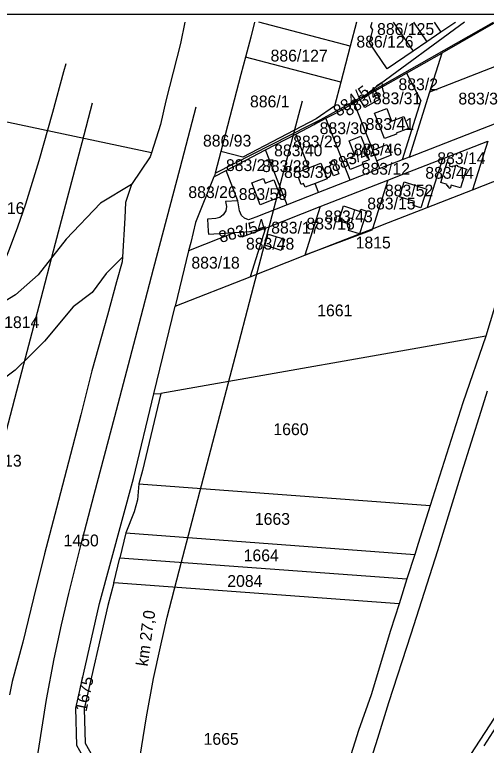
# Model space of a CAD drawing. Extents: x -583889 to -582839, y -1166553 to -1165065.
# Drawn here: x -583391.3 to -583111.8, y -1165500.8 to -1165067.8 of the extents above; entities that cross this region are included whole.
import ezdxf

# ---------------------------------------------------------------- set-up
doc = ezdxf.new("R2010")
doc.units = 0
for name, color, linetype in [('14', 7, 'Continuous'), ('56', 7, 'Continuous'), ('Popis cest', 7, 'Continuous'), ('Vrstva 1', 7, 'Continuous'), ('Vrstva 2', 7, 'Continuous')]:
    doc.layers.add(name, color=color, linetype=linetype)

msp = doc.modelspace()

# ---------------------------------------------------------------- linework, layer by layer
at = {"layer": '56'}
msp.add_lwpolyline([(-583888.67, -1166552.78), (-582838.67, -1166552.78), (-582838.67, -1165067.78), (-583888.67, -1165067.78), (-583888.67, -1166552.78)], dxfattribs=at)
at = {"layer": 'Vrstva 1'}
for points in [[(-583408.88, -1165239.76), (-583401.31, -1165223.4), (-583394.39, -1165206.81), (-583389.42, -1165193.59), (-583384.69, -1165179.92), (-583376.75, -1165154.16), (-583368.72, -1165125.58), (-583362.12, -1165101.52), (-583360.8, -1165096.71)], [(-583463.73, -1166045.43), (-583461.96, -1166001.15), (-583459.73, -1165944.95), (-583457.83, -1165897.51), (-583455.75, -1165845), (-583453.88, -1165797.97), (-583451.76, -1165745.07), (-583447.63, -1165643.26), (-583446.86, -1165623.99), (-583445.81, -1165599.54), (-583444.66, -1165577.37), (-583442.03, -1165542.78), (-583439.67, -1165520.04), (-583436.68, -1165496.55), (-583431.49, -1165463.54), (-583426.63, -1165437.64), (-583422.05, -1165416.22), (-583417.44, -1165396.54), (-583410.09, -1165367.4), (-583389.99, -1165290.81), (-583376.8, -1165240.45), (-583367.04, -1165203.24), (-583351.37, -1165143.48), (-583345.2, -1165119.98)], [(-583317.86, -1165513.43), (-583313.23, -1165483.92), (-583308.97, -1165461.26), (-583304.95, -1165442.46), (-583300.84, -1165424.92), (-583293.87, -1165397.32), (-583273.91, -1165321.23), (-583260.72, -1165270.87), (-583250.96, -1165233.68), (-583235.29, -1165173.92), (-583222.96, -1165126.91), (-583220.86, -1165118.88)], [(-583391.81, -1165747.49), (-583389.84, -1165698.95), (-583387.68, -1165645.68), (-583386.91, -1165626.47), (-583385.88, -1165602.38), (-583384.78, -1165581.2), (-583382.27, -1165548.16), (-583380.06, -1165526.93), (-583377.27, -1165504.99), (-583372.36, -1165473.73), (-583367.8, -1165449.45), (-583363.5, -1165429.34), (-583359.14, -1165410.73), (-583351.98, -1165382.36), (-583344.08, -1165352.25), (-583331.95, -1165306.02), (-583318.76, -1165255.66), (-583309, -1165218.46), (-583293.33, -1165158.7), (-583283.82, -1165122.45)]]:
    msp.add_lwpolyline(points, dxfattribs=at)
at = {"layer": 'Vrstva 2'}
for p, q in [((-583192.52, -1165086.48), (-583246.64, -1165072.33)), ((-583188.82, -1165072.33), (-583192.52, -1165086.48)), ((-583182.09, -1165114.62), (-583107.53, -1165072.33)), ((-583167.06, -1165072.33), (-583155.29, -1165089.5)), ((-583154.94, -1165072.33), (-583147.04, -1165083.85)), ((-583142.81, -1165072.33), (-583138.79, -1165078.2)), ((-583130.54, -1165072.55), (-583138.79, -1165078.2)), ((-583106.15, -1165072.33), (-583138.25, -1165090.53)), ((-583130.69, -1165072.33), (-583130.54, -1165072.55)), ((-583130.22, -1165072.33), (-583130.54, -1165072.55)), ((-583138.79, -1165078.2), (-583147.04, -1165083.85)), ((-583060.04, -1165080.27), (-583145.52, -1165113.73)), ((-583147.04, -1165083.85), (-583155.29, -1165089.5)), ((-583192.52, -1165086.48), (-583198.08, -1165107.77)), ((-583198.08, -1165107.77), (-583254.56, -1165093)), ((-583159.2, -1165102.41), (-583138.25, -1165090.53)), ((-583138.25, -1165090.53), (-583145.52, -1165113.73)), ((-583177.74, -1165112.93), (-583159.2, -1165102.41)), ((-583209.97, -1165129.86), (-583182.09, -1165114.62)), ((-583185.39, -1165117.27), (-583177.74, -1165112.93)), ((-583182.09, -1165114.62), (-583185.39, -1165117.27)), ((-583145.52, -1165113.73), (-583157.61, -1165152.25)), ((-583190.15, -1165119.97), (-583186.69, -1165118.01)), ((-583179.13, -1165148.17), (-583190.15, -1165119.97)), ((-583186.69, -1165118.01), (-583185.39, -1165117.27)), ((-583157.61, -1165152.25), (-583071.94, -1165118.73)), ((-583310.2, -1165149.72), (-583419.03, -1165126.58)), ((-583213.82, -1165132.82), (-583206.95, -1165129.23)), ((-583192.59, -1165165.93), (-583206.95, -1165129.23)), ((-583224.78, -1165138.54), (-583213.82, -1165132.82)), ((-583213.82, -1165132.82), (-583209.97, -1165129.86)), ((-583242.61, -1165147.85), (-583224.78, -1165138.54)), ((-583216.94, -1165158.58), (-583224.78, -1165138.54)), ((-583137.89, -1165153.24), (-583111.02, -1165142.73)), ((-583111.02, -1165142.73), (-583120.08, -1165171.59)), ((-583269.11, -1165148.86), (-583272.42, -1165161.67)), ((-583266.01, -1165160.07), (-583242.61, -1165147.85)), ((-583229.84, -1165180.5), (-583242.61, -1165147.85)), ((-583176.72, -1165154.36), (-583179.13, -1165148.17)), ((-583174.9, -1165159.01), (-583176.72, -1165154.36)), ((-583161.79, -1165153.89), (-583174.9, -1165159.01)), ((-583157.61, -1165152.25), (-583161.79, -1165153.89)), ((-583137.89, -1165153.24), (-583146.95, -1165182.1)), ((-583174.9, -1165159.01), (-583192.59, -1165165.93)), ((-583120.08, -1165171.59), (-583084.11, -1165157.51)), ((-583273.25, -1165163.85), (-583266.01, -1165160.07)), ((-583258.98, -1165178.07), (-583266.01, -1165160.07)), ((-583211.22, -1165173.22), (-583213.34, -1165167.8)), ((-583192.59, -1165165.93), (-583211.22, -1165173.22)), ((-583210.23, -1165181.54), (-583170.28, -1165165.91)), ((-583170.28, -1165165.91), (-583179.34, -1165194.77)), ((-583146.95, -1165182.1), (-583120.08, -1165171.59)), ((-583211.22, -1165173.22), (-583229.84, -1165180.5)), ((-583242.78, -1165194.27), (-583210.23, -1165181.54)), ((-583210.23, -1165181.54), (-583219.29, -1165210.4)), ((-583242.78, -1165194.27), (-583251.84, -1165223.13)), ((-583260.77, -1165196.96), (-583288.23, -1165207.7)), ((-583260.77, -1165196.96), (-583257.89, -1165196.79)), ((-583288.23, -1165207.7), (-583296.29, -1165240.52)), ((-583251.84, -1165223.13), (-583219.29, -1165210.4)), ((-583296.29, -1165240.52), (-583251.84, -1165223.13)), ((-583308.83, -1165292.52), (-583296.29, -1165240.52)), ((-583112.09, -1165258.27), (-583304.62, -1165292.26)), ((-583308.83, -1165292.52), (-583304.62, -1165292.26)), ((-583317.66, -1165345.79), (-583145.07, -1165358.62)), ((-583325.5, -1165374.92), (-583329.03, -1165389.78)), ((-583325.5, -1165374.92), (-583154.3, -1165387.67)), ((-583154.3, -1165387.67), (-583158.9, -1165402.17)), ((-583332.55, -1165404.6), (-583329.03, -1165389.78)), ((-583329.03, -1165389.78), (-583158.9, -1165402.17)), ((-583158.9, -1165402.17), (-583163.57, -1165416.9)), ((-583163.57, -1165416.9), (-583332.55, -1165404.6))]:
    msp.add_line(p, q, dxfattribs=at)
for points in [[(-583290.39, -1165072.33), (-583293.05, -1165084.81), (-583301.65, -1165118.91), (-583304.95, -1165132.91), (-583310.2, -1165149.72)], [(-583249.12, -1165072.33), (-583251.38, -1165081.18), (-583254.56, -1165093)], [(-583124.73, -1165072.33), (-583177.59, -1165111.01), (-583182.09, -1165114.62)], [(-583155.29, -1165089.5), (-583170.56, -1165099.96), (-583181.14, -1165084.5), (-583179.11, -1165076.73), (-583180.24, -1165075.09), (-583179.52, -1165072.33)], [(-583254.56, -1165093), (-583257.31, -1165103.21), (-583269.11, -1165148.86)], [(-583159.2, -1165102.41), (-583150.74, -1165118.66), (-583161.79, -1165153.89)], [(-583198.08, -1165107.77), (-583201.79, -1165121.97), (-583212.74, -1165129.47), (-583256.06, -1165152.27), (-583269.11, -1165148.86)], [(-583177.74, -1165112.93), (-583174.94, -1165117.84), (-583183.93, -1165122.9), (-583186.69, -1165118.01)], [(-583206.95, -1165129.23), (-583201, -1165126.12), (-583190.15, -1165119.97)], [(-583178.04, -1165126.19), (-583170.85, -1165123.38), (-583167.95, -1165130.86), (-583160.8, -1165128.06), (-583158.01, -1165135.2), (-583165.21, -1165138.06), (-583165.03, -1165138.53), (-583172.2, -1165141.29), (-583178.04, -1165126.19)], [(-583272.42, -1165161.67), (-583216.55, -1165133.21), (-583209.97, -1165129.86)], [(-583194.84, -1165153.37), (-583189.72, -1165151.36), (-583193.17, -1165142.57), (-583186.16, -1165139.84), (-583182.54, -1165149.06), (-583183.1, -1165149.27), (-583181.31, -1165153.85), (-583185.41, -1165155.45), (-583184.97, -1165156.57), (-583192.44, -1165159.48), (-583194.84, -1165153.37)], [(-583179.13, -1165148.17), (-583170.78, -1165144.83), (-583168.3, -1165151), (-583176.72, -1165154.36)], [(-583310.2, -1165149.72), (-583310.93, -1165152.06), (-583322.15, -1165168.47)], [(-583202.27, -1165154.28), (-583199.18, -1165162.12), (-583202.45, -1165163.41), (-583204.81, -1165157.44), (-583203.78, -1165157.04), (-583204.52, -1165155.17), (-583202.27, -1165154.28)], [(-583170.28, -1165165.91), (-583160.72, -1165162.17), (-583137.89, -1165153.24)], [(-583135.17, -1165168.49), (-583138.74, -1165167.33), (-583135, -1165155.19), (-583133.37, -1165155.73), (-583133.88, -1165157.4), (-583131.93, -1165157.97), (-583131.75, -1165157.37), (-583130.94, -1165157.65), (-583130.79, -1165157.12), (-583129.97, -1165157.39), (-583129.81, -1165156.86), (-583128.97, -1165157.1), (-583129.16, -1165157.64), (-583124.03, -1165159.23), (-583123.33, -1165159.47), (-583123.47, -1165159.94), (-583123.86, -1165159.84), (-583127.2, -1165170.5), (-583132.64, -1165168.78), (-583133.2, -1165170.78), (-583134.02, -1165170.52), (-583133.86, -1165170.02), (-583134.66, -1165169.74), (-583134.5, -1165169.23), (-583135.31, -1165168.95), (-583135.17, -1165168.49)], [(-583213.34, -1165167.8), (-583219.24, -1165170.11), (-583220.15, -1165167.79), (-583221.58, -1165168.36), (-583223.16, -1165164.33), (-583221.71, -1165163.77), (-583222.84, -1165160.89), (-583216.94, -1165158.58)], [(-583216.94, -1165158.58), (-583209.83, -1165155.79), (-583206.23, -1165165.02), (-583213.34, -1165167.8)], [(-583273.25, -1165163.85), (-583284.11, -1165190.92), (-583286.96, -1165202.76), (-583288.23, -1165207.7)], [(-583272.42, -1165161.67), (-583272.88, -1165163.39), (-583273.25, -1165163.85)], [(-583250.8, -1165167.53), (-583246.62, -1165165.93), (-583243.85, -1165164.96), (-583242.84, -1165167.68), (-583237.68, -1165165.6), (-583233.77, -1165175.77), (-583245.84, -1165180.42), (-583250.8, -1165167.53)], [(-583154.41, -1165178.52), (-583163.24, -1165175.74), (-583160.51, -1165166.95), (-583147.19, -1165171.14), (-583150.71, -1165182.29), (-583155.13, -1165180.9), (-583154.41, -1165178.52)], [(-583322.15, -1165168.47), (-583340.5, -1165179.46), (-583360.81, -1165200.75), (-583377.25, -1165221.89), (-583390.68, -1165233.74), (-583416.76, -1165249.61), (-583440.61, -1165276.22), (-583445.47, -1165291.1), (-583456.44, -1165295.04)], [(-583322.15, -1165168.47), (-583325.57, -1165179.12), (-583326, -1165188.3), (-583327.43, -1165211.57)], [(-583258.98, -1165178.07), (-583266.29, -1165178.5), (-583265.88, -1165181.52), (-583266.18, -1165183.96), (-583267.73, -1165186.48), (-583269.73, -1165187.92), (-583272.1, -1165188.61), (-583277.05, -1165188.92), (-583276.57, -1165196.2), (-583276.47, -1165197.91), (-583260.77, -1165196.96)], [(-583229.84, -1165180.5), (-583248.47, -1165187.79), (-583252.75, -1165189.46), (-583255.2, -1165188.46), (-583256.97, -1165186.76), (-583258.07, -1165184), (-583258.98, -1165178.07)], [(-583186.95, -1165197.75), (-583193.56, -1165195.75), (-583192.62, -1165192.82), (-583193.18, -1165191.92), (-583199.34, -1165189.93), (-583196.55, -1165181.19), (-583186.6, -1165184.42), (-583186.22, -1165183.15), (-583182.66, -1165184.28), (-583186.95, -1165197.75)], [(-583179.34, -1165194.77), (-583169.78, -1165191.03), (-583146.95, -1165182.1)], [(-583257.89, -1165196.79), (-583257.11, -1165196.74), (-583252.11, -1165196.21), (-583249.62, -1165195.75), (-583242.78, -1165194.27)], [(-583242.78, -1165194.27), (-583256.75, -1165199.73), (-583257.89, -1165196.79)], [(-583241.02, -1165197.83), (-583231.44, -1165200.93), (-583233.47, -1165207.47), (-583243.14, -1165204.44), (-583241.02, -1165197.83)], [(-583219.29, -1165210.4), (-583186.95, -1165197.75), (-583179.34, -1165194.77)], [(-583179.34, -1165194.77), (-583179.66, -1165195.53), (-583219.29, -1165210.4)], [(-583327.43, -1165211.57), (-583337.15, -1165221.16), (-583345.28, -1165232.38), (-583356.63, -1165240.96), (-583373.5, -1165261.36), (-583381.99, -1165269.78), (-583390.9, -1165278.52), (-583409.51, -1165292.26), (-583429.18, -1165300.2), (-583454.83, -1165307.19)], [(-583327.43, -1165211.57), (-583327.59, -1165214.21), (-583330.92, -1165226.21), (-583336.19, -1165245.95), (-583345.5, -1165278.93), (-583352.15, -1165304.95), (-583359.3, -1165333.07), (-583366.57, -1165360.34), (-583373.53, -1165387.37), (-583380.03, -1165413.66), (-583386.52, -1165439.72), (-583392.75, -1165463.03), (-583394.35, -1165470.85)], [(-583097.01, -1165208.5), (-583101.24, -1165222.44), (-583112.09, -1165258.27)], [(-583112.09, -1165258.27), (-583125.85, -1165297.89), (-583145.07, -1165358.62)], [(-583361.04, -1165570.69), (-583342.57, -1165547.76), (-583341.85, -1165530.97), (-583343.72, -1165519.91), (-583354.54, -1165500.86), (-583355.11, -1165478.77), (-583350.44, -1165458.56), (-583341.01, -1165416.67), (-583320.9, -1165342.6), (-583308.83, -1165292.52)], [(-583304.62, -1165292.26), (-583315.52, -1165337.89), (-583317.66, -1165345.79)], [(-583184.72, -1165523.62), (-583182.81, -1165517.68), (-583176.05, -1165496.65), (-583169.59, -1165475.46), (-583156.46, -1165434.65), (-583140.6, -1165385.28), (-583126.45, -1165339.09), (-583115, -1165302.85), (-583111.16, -1165290.82)], [(-583150.03, -1165547.02), (-583146.45, -1165545.26), (-583081.48, -1165445.65), (-583060.78, -1165413.9), (-582999.79, -1165321.21), (-583000.42, -1165318.79)], [(-583317.66, -1165345.79), (-583318.57, -1165355.26), (-583320.51, -1165362.38), (-583325.5, -1165374.92)], [(-583145.07, -1165358.62), (-583152.23, -1165381.21), (-583154.3, -1165387.67)], [(-583332.55, -1165404.6), (-583336.16, -1165417.88), (-583350.1, -1165479.27), (-583349.57, -1165499.48), (-583339.8, -1165516.68), (-583336.86, -1165530.49), (-583338.68, -1165550.89), (-583347.2, -1165561.47), (-583348.01, -1165573.19)], [(-583163.57, -1165416.9), (-583168.61, -1165432.78), (-583180.14, -1165470.95), (-583187.62, -1165491.96), (-583193.05, -1165509.63), (-583194.86, -1165515.1)], [(-583078.55, -1165447.56), (-583104.44, -1165487.27), (-583113.44, -1165501.07)]]:
    msp.add_lwpolyline(points, dxfattribs=at)

# ---------------------------------------------------------------- texts
at = {"layer": '14'}
msp.add_text('km 27,0', height=7, rotation=82.0212, dxfattribs=at).set_placement((-583312.5, -1165454.26))
at = {"layer": 'Popis cest'}
for s, p in [('886/125', (-583176.6, -1165079.83)), ('886/126', (-583188.85, -1165087.31)), ('886/127', (-583239.68, -1165095.58)), ('883/2', (-583163.92, -1165112.56)), ('886/1', (-583251.86, -1165122.73)), ('883/31', (-583179.05, -1165120.88)), ('883/3', (-583128.41, -1165121.04)), ('883/41', (-583183.35, -1165136.11)), ('883/30', (-583210.6, -1165138.6)), ('886/93', (-583279.73, -1165145.99)), ('883/29', (-583226.29, -1165146.48)), ('883/40', (-583237.59, -1165151.74)), ('883/46', (-583190.4, -1165151.24)), ('883/14', (-583140.94, -1165156.38)), ('883/27', (-583266.13, -1165160.49)), ('883/28', (-583244.77, -1165161.09)), ('883/12', (-583185.74, -1165162.64)), ('883/39', (-583231.71, -1165164.56)), ('883/44', (-583148.02, -1165165.05)), ('883/52', (-583171.94, -1165175.53)), ('883/26', (-583288.38, -1165176.48)), ('883/59', (-583258.52, -1165177.63)), ('883/15', (-583182.42, -1165183.23)), ('1816', (-583406.3, -1165185.94)), ('883/43', (-583207.79, -1165190.86)), ('883/16', (-583218.44, -1165195.14)), ('883/17', (-583239.32, -1165197.53)), ('883/48', (-583254.26, -1165207.05)), ('1815', (-583189.29, -1165206.35)), ('883/18', (-583286.58, -1165218.29)), ('1661', (-583212.05, -1165246.58)), ('1814', (-583397.49, -1165253.55)), ('1660', (-583238.01, -1165316.98)), ('1813', (-583407.93, -1165335.62)), ('1663', (-583248.99, -1165370.14)), ('1450', (-583362.28, -1165382.89)), ('1664', (-583255.63, -1165391.72)), ('2084', (-583265.32, -1165406.91)), ('1665', (-583279.38, -1165500.5))]:
    msp.add_text(s, height=7, dxfattribs=at).set_placement(p)
for s, rotation, p in [('883/47', 32, (-583193.77, -1165128.32)), ('884/5', 36, (-583199.35, -1165128.61)), ('883/42', 22, (-583202.48, -1165161.15)), ('883/54', 16, (-583269.24, -1165203.13)), ('1675', 78, (-583348.76, -1165481.23))]:
    msp.add_text(s, height=7, rotation=rotation, dxfattribs=at).set_placement(p)

doc.saveas('drawing.dxf')
